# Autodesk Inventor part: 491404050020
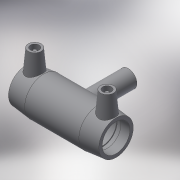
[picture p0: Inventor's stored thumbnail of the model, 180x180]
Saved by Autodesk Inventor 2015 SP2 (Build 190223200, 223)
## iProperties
Created: 2017-06
Part Number: 491404050020
Material: Generic
Description: PLASSON REDUCING TEE 50x20x50
Document SubType Name: Modeling
Designer: KIM
Mass: 57.3761 g
Surface Area: 241.06 cm^2
Volume: 57.3761 cm^3
Density: 1 g/cm^3
Appearance: Default
Author: KIM
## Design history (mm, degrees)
derived "491404.ipt"
feature "Solid1::491404.ipt"
tag "TaggingFeature1"
body "Solid1"
other parameters: "d0" = 139, "d2" = 68, "d3" = 48, "d4" = 27.8, "d5" = 61.2, "d6" = 47.5, "d8" = 168 deg, "d10" = 19.2, "d11" = 6.4, "d13" = 139, "d14" = 17.6296, "d17" = 45, "d19" = 3.52592, "d20" = 168 deg, "d22" = 63.24, "d23" = 68, "d25" = 135 deg, "d26" = 97.3, "d29" = 52, "d30" = 15, "d31" = 55.6, "d34" = 5 deg, "d35" = 15, "d39" = 5 deg, "d41" = 4, "d42" = 14, "d43" = 0, "d45" = 4, "d46" = 6, "d47" = 0, "d48" = -78, "d51" = 0, "d52" = 16, "d54" = 0, "d55" = 61.2, "d56" = 68, "d57" = 48.65, "d58" = 135 deg, "d59" = 48, "d60" = 48, "d61" = 135 deg, "d62" = 78, "d72" = 63.245, "d73" = 31.6225, "d74" = -78, "d75" = 21, "d77" = 0, "d78" = 16, "d80" = 0, "d82" = 44, "d83" = 0, "d84" = 3, "d85" = 0, "d86" = 16, "d87" = 61.9752, "d88" = 6.4, "d89" = 3, "d90" = 0, "L_" = 139, "L_1" = 48, "D_" = 68, "A_" = 52, "d_2" = 12, "H_" = 78
